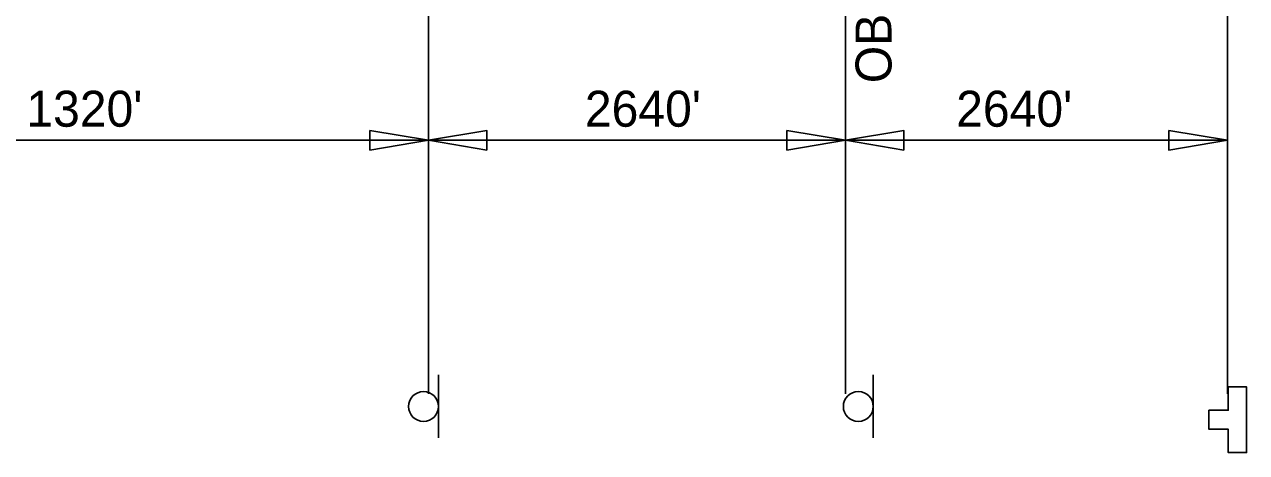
# Model space of a CAD drawing. Extents: x 2155255 to 2162649, y 140388 to 141878.
# Drawn here: x 2156920.8 to 2157124.8, y 141189.1 to 141260.5 of the extents above; entities that cross this region are included whole.
import ezdxf

# ---------------------------------------------------------------- set-up
doc = ezdxf.new("R2010")
doc.units = 0
for name, color, linetype in [('Default', 7, 'Continuous'), ('PR_Dimensions1', 7, 'Continuous'), ('PR_Traffic_Control_Devices_Temp', 7, 'Continuous'), ('PR_Traffic_Temp_Txt', 7, 'Continuous')]:
    doc.layers.add(name, color=color, linetype=linetype)

# ---------------------------------------------------------------- blocks, each defined once
blk = doc.blocks.new('TCSIGN')
at = {"layer": 'Default'}
blk.add_line((5.26, 2.5), (-5.26, 2.5), dxfattribs=at)
blk.add_circle((0, 0), 2.5, dxfattribs=at)
blk = doc.blocks.new('Arrowhd')
at = {"layer": 'Default'}
blk.add_lwpolyline([(0.3175, -0.0529), (0.3175, 0.0529), (0, 0)], close=True, dxfattribs=at)
blk = doc.blocks.new('PR-TCSIGN_rev')
at = {"layer": 'Default'}
blk.add_lwpolyline([(-5.47, 0), (-1.58, 0), (-1.58, -3.22), (1.58, -3.22), (1.58, 0), (5.47, 0), (5.47, 3.06), (-5.47, 3.06)], close=True, dxfattribs=at)
blk.add_lwpolyline([(1.58, 0), (5.47, 0), (5.47, 3.06), (-5.47, 3.06), (-5.47, 0), (-1.58, 0), (-1.58, -3.22), (1.58, -3.22), (1.58, 0)], dxfattribs=at)

msp = doc.modelspace()

# ---------------------------------------------------------------- linework, layer by layer
at = {"layer": 'PR_Dimensions1'}
for p, q in [((2157057.81, 141198.84), (2157057.81, 141379.68)), ((2157121.55, 141198.84), (2157121.55, 141354.06)), ((2156988.21, 141198.84), (2156988.21, 141309.35)), ((2156988.21, 141241.15), (2156892.55, 141241.15)), ((2157057.81, 141241.15), (2156988.21, 141241.15)), ((2157121.55, 141241.15), (2157057.81, 141241.15))]:
    msp.add_line(p, q, dxfattribs=at)

# ---------------------------------------------------------------- block references
at = {"layer": 'PR_Dimensions1', "xscale": 30.761459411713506, "yscale": 30.761459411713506, "rotation": 180}
for p in [(2156988.21, 141241.15), (2157057.81, 141241.15), (2157121.55, 141241.15)]:
    msp.add_blockref('Arrowhd', p, dxfattribs=at)
at = {"layer": 'PR_Dimensions1', "xscale": 30.761459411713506, "yscale": 30.761459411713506}
for p in [(2156988.21, 141241.15), (2157057.81, 141241.15)]:
    msp.add_blockref('Arrowhd', p, dxfattribs=at)
at = {"layer": 'PR_Traffic_Control_Devices_Temp', "rotation": -90.00000000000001}
for name, p in [('TCSIGN', (2156987.39, 141196.74)), ('TCSIGN', (2157059.96, 141196.74)), ('PR-TCSIGN_rev', (2157121.7, 141194.52))]:
    msp.add_blockref(name, p, dxfattribs=at)

# ---------------------------------------------------------------- texts
at = {"layer": 'PR_Traffic_Temp_Txt'}
for s, rotation, p in [('OBEY ALL TRAFFIC SIGNS', 90, (2157065.5, 141250.68)), ("1320'", 360, (2156921.1, 141243.42)), ("2640'", 360, (2157014.32, 141243.42)), ("2640'", 360, (2157076.29, 141243.42))]:
    msp.add_text(s, height=6, rotation=rotation, dxfattribs=at).set_placement(p)

doc.saveas('drawing.dxf')
